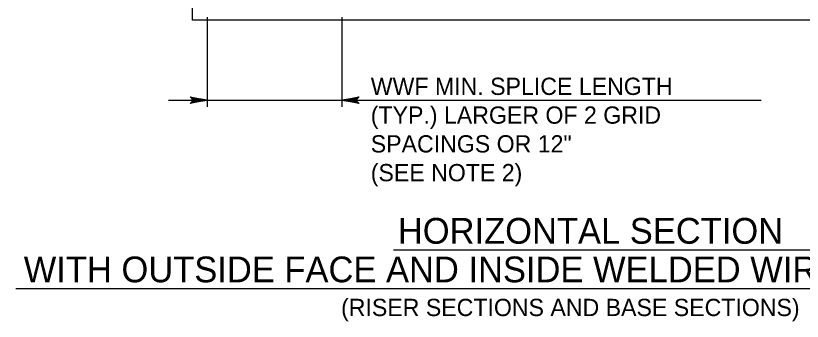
# Model space of a CAD drawing. Extents: x -6420 to 49575, y -4552 to 11624.
# Drawn here: x 5730 to 6177.9, y 2994.4 to 3168.6 of the extents above; entities that cross this region are included whole.
import ezdxf

# ---------------------------------------------------------------- set-up
doc = ezdxf.new("R2010")
doc.units = 0
doc.layers.add('1', color=7, linetype='Continuous')

msp = doc.modelspace()

# ---------------------------------------------------------------- linework, layer by layer
at = {"layer": '1'}
for p, q in [((5839.06, 3167.75), (5839.06, 3116.64)), ((5915.71, 3167.75), (5915.71, 3116.64)), ((5816.94, 3120.45), (6154.51, 3120.45)), ((5945.1, 3035.17), (6209.28, 3035.17)), ((5730.05, 3013.17), (6424.12, 3013.17))]:
    msp.add_line(p, q, dxfattribs=at)
msp.add_lwpolyline([(5830.73, 3585.71), (6319.63, 3585.71), (6319.63, 3166.1), (5830.73, 3166.1)], close=True, dxfattribs=at)
for points in [[(5839.06, 3120.45), (5829.28, 3118.61), (5829.65, 3118.88), (5830.03, 3119.14), (5830.22, 3119.47), (5830.42, 3119.79), (5830.47, 3120.12), (5830.53, 3120.45), (5830.47, 3120.78), (5830.42, 3121.11), (5830.22, 3121.43), (5830.03, 3121.76), (5829.65, 3122.02), (5829.28, 3122.28), (5839.06, 3120.45), (5829.65, 3122.02), (5830.03, 3121.76), (5839.06, 3120.45), (5830.22, 3121.43), (5830.42, 3121.11), (5839.06, 3120.45), (5830.47, 3120.78), (5830.53, 3120.45), (5839.06, 3120.45), (5830.47, 3120.12), (5830.42, 3119.79), (5839.06, 3120.45), (5830.22, 3119.47), (5830.03, 3119.14), (5839.06, 3120.45), (5829.65, 3118.88)], [(5915.71, 3120.45), (5925.49, 3122.28), (5925.12, 3122.02), (5924.74, 3121.76), (5924.55, 3121.43), (5924.35, 3121.11), (5924.29, 3120.78), (5924.24, 3120.45), (5924.29, 3120.12), (5924.35, 3119.79), (5924.55, 3119.47), (5924.74, 3119.14), (5925.12, 3118.88), (5925.49, 3118.61), (5915.71, 3120.45), (5925.12, 3118.88), (5924.74, 3119.14), (5915.71, 3120.45), (5924.55, 3119.47), (5924.35, 3119.79), (5915.71, 3120.45), (5924.29, 3120.12), (5924.24, 3120.45), (5915.71, 3120.45), (5924.29, 3120.78), (5924.35, 3121.11), (5915.71, 3120.45), (5924.55, 3121.43), (5924.74, 3121.76), (5915.71, 3120.45), (5925.12, 3122.02)]]:
    msp.add_lwpolyline(points, dxfattribs=at)

# ---------------------------------------------------------------- texts
for s, height, p in [('WWF MIN. SPLICE LENGTH', 9.8425, (5932.19, 3123.42)), ('(TYP.) LARGER OF 2 GRID', 9.8425, (5932.19, 3107.02)), ('SPACINGS OR 12"', 9.8425, (5932.19, 3090.62)), ('(SEE NOTE 2)', 9.8425, (5932.19, 3074.21)), ('HORIZONTAL SECTION', 14.6898, (5947.61, 3038.6)), ('WITH OUTSIDE FACE AND INSIDE WELDED WIRE FABRIC', 14.6898, (5734.61, 3016.61)), ('(RISER SECTIONS AND BASE SECTIONS)', 9.8425, (5915.29, 2997.35))]:
    msp.add_text(s, height=height, dxfattribs=at).set_placement(p)

doc.saveas('drawing.dxf')
